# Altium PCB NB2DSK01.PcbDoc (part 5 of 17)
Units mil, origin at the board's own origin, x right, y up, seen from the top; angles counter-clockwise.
Board outline 11815 x 6500.03 mil, 8 copper layers (Top Layer, MidLayer1, MidLayer2, GND, PWR, MidLayer3, MidLayer4, Bottom Layer), stack 74.62 mil thick; 798 components, 1002 nets, 3927 pads, 3182 vias.
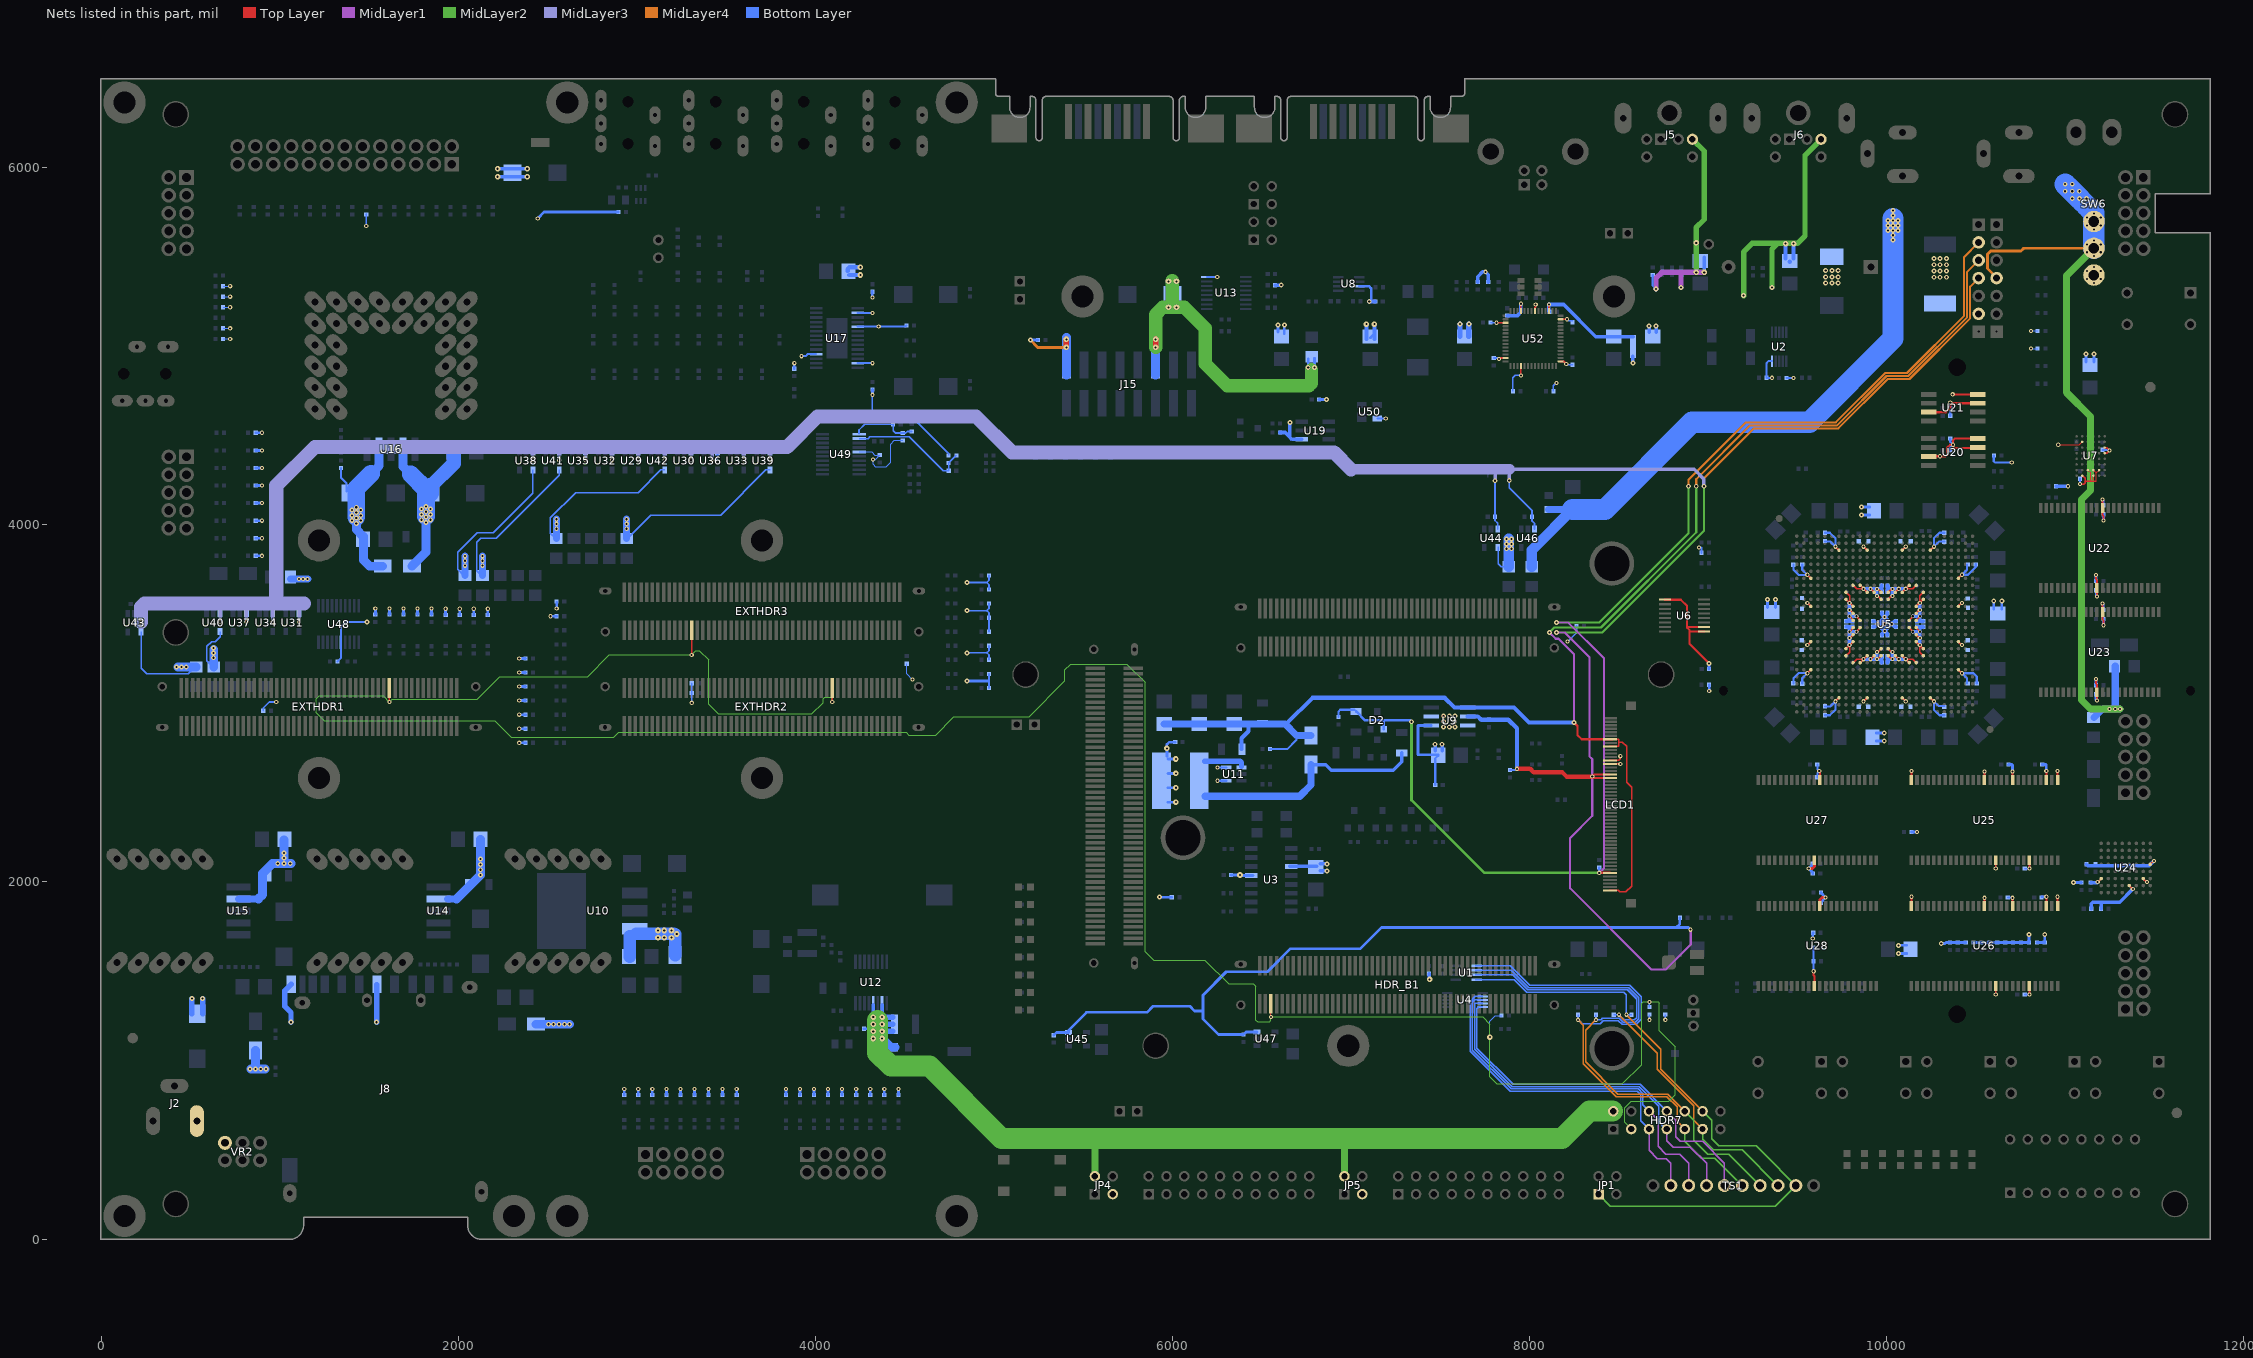
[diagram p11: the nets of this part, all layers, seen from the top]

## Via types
v1: diameter 23.62, hole 11.81, Top Layer to Bottom Layer, tented both sides, 1950 vias
v2: diameter 27.56, hole 11.81, Top Layer to Bottom Layer, tented both sides, 679 vias
v3: diameter 23.62, hole 11.81, Top Layer to Bottom Layer, 194 vias
v4: diameter 31.5, hole 11.81, Top Layer to Bottom Layer, tented both sides, 178 vias
v5: diameter 21.65, hole 11.81, Top Layer to Bottom Layer, tented both sides, 67 vias
v6: diameter 23.62, hole 11.81, Top Layer to Bottom Layer, tented bottom, 53 vias
v7: diameter 26, hole 11.81, Top Layer to Bottom Layer, tented both sides, 21 vias
v8: diameter 26, hole 11.81, Top Layer to Bottom Layer, 13 vias
v9: diameter 28, hole 11.81, Top Layer to Bottom Layer, 8 vias
v10: diameter 25.59, hole 11.81, Top Layer to Bottom Layer, tented both sides, 7 vias
v11: diameter 39.37, hole 11.81, Top Layer to Bottom Layer, tented both sides, 5 vias
v12: diameter 30, hole 11.81, Top Layer to Bottom Layer, 3 vias
v13: diameter 30, hole 11.81, Top Layer to Bottom Layer, tented both sides, 2 vias
v14: diameter 23, hole 11.81, Top Layer to Bottom Layer, tented both sides, 1 vias
v15: diameter 26.56, hole 11.81, Top Layer to Bottom Layer, tented both sides, 1 vias

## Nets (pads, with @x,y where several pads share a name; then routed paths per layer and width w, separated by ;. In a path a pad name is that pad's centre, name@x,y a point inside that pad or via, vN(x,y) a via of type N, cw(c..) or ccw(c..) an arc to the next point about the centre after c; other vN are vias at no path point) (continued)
3V3: C10.1 C11.1 C14.1 C15.1 C54.1 C55.1 C56.1 C57.1 C58.1 C59.1 C60.1 C61.1 C62.1 C63.1 C64.1 C65.1 C66.1 C67.1 C68.1 C69.1 C70.1 C71.1 C72.1 C73.1 C74.1 C75.1 C76.1 C77.1 C78.1 C79.1 C80.1 C81.1 C82.1 C83.1 C84.1 C85.1 C86.1 C87.1 C88.1 C89.1 C90.1 C91.1 C92.1 C93.1 C94.1 C95.1 C96.1 C97.1 C98.1 C99.1 C100.1 C101.1 C102.1 C103.1 C104.1 C105.1 C106.1 C107.1 C108.1 C109.1 C110.1 C111.1 C112.1 C113.1 C117.1 C121.1 C122.1 C123.1 C124.1 C125.1 C126.1 C154.1 C157.1 C158.1 C161.1 C162.1 C167.1 C168.1 C199.1 C200.2 C201.1 C202.2 C203.1 C204.1 C205.1 C206.1 C207.1 C208.1 C209.1 C210.1 C211.1 C212.1 C213.1 C214.1 C215.1 C216.1 C217.1 C218.1 C219.1 C220.1 C221.1 C222.1 C223.1 C224.1 C225.1 C226.1 C227.1 C228.1 C229.1 C230.1 C231.1 C232.1 C233.1 C234.1 C254.1 C255.1 C263.2 C264.2 C265.2 C266.1 C267.1 C268.1 D6.2 D7.2 D8.1 J8.4 J8.COM J15.16 JP4.3 JP5.3 LCD1.37 LCD1.38 NT5.1 R1.2 R6.1 R7.1 R10.2 R12.1 R18.2 R20.1 R34.2 R47.2 R52.1 R79.2 R135.2 R137.2 R142.2 R143.2 R144.2 R145.2 R146.2 R147.2 R148.2 R149.2 R150.2 R151.2 R152.2 R153.1 R154.1 R155.2 R156.1 R157.2 R158.1 R159.1 R160.2 R171.1 R172.1 R173.1 R177.1 R183.2 R190.2 R191.2 R192.2 R193.2 R198.2 R199.2 R200.2 R201.2 R206.2 R208.2 R209.2 R210.2 R211.2 R216.2 R217.2 R218.2 R219.2 R224.2 R226.2 R227.2 R228.2 R229.2 R234.2 R235.2 R236.2 R237.2 R242.2 R244.2 R245.2 R246.2 R247.2 R252.2 R253.2 R254.2 R255.2 R260.2 R262.2 R263.2 R264.2 R265.2 R270.2 R271.2 R272.2 R273.2 R278.2 R280.2 R281.2 R282.2 R283.2 R288.2 R289.2 R290.2 R291.2 R296.1 R297.2 R298.2 R299.2 R300.2 R303.1 R304.1 R314.2 R316.2 R318.1 R319.1 TP12.1 U2.10 U3.3 U3.13 U5.AD7 U5.AD11 U5.AD16 U5.AD20 U5.C7 U5.C11 U5.C16 U5.C20 U5.G3 U5.G24 U5.H9 U5.H10 U5.H17 U5.H18 U5.J8 U5.J11 U5.J12 U5.J13 U5.J14 U5.J15 U5.J16 U5.J19 U5.K8 U5.K13 U5.K14 U5.K19 U5.L3 U5.L9 U5.L18 U5.L24 U5.M9 U5.M18 U5.N9 U5.N10 U5.N17 U5.N18 U5.P9 U5.P10 U5.P17 U5.P18 U5.R9 U5.R18 U5.T3 U5.T9 U5.T18 U5.T24 U5.U8 U5.U13 U5.U14 U5.U19 U5.V8 U5.V11 U5.V12 U5.V13 U5.V14 U5.V15 U5.V16 U5.V19 U5.W9 U5.W10 U5.W17 U5.W18 U5.Y3 U5.Y24 U6.1 U6.9 U6.10 U7.B2 U7.C6 U7.D6 U7.G3 U7.G4 U7.G5 U7.H2 U7.H4 U8.3 U13.16 U14.2 U15.2 U16.4 U19.4 U20.3 U20.7 U20.8 U21.3 U21.7 U21.8 U22.11 U22.33 U23.11 U23.33 U24.D8 U24.F1 U24.F7 U24.G5 U25.1 U25.3 U25.9 U25.14 U25.27 U25.43 U25.49 U26.1 U26.3 U26.9 U26.14 U26.27 U26.43 U26.49 U27.11 U27.33 U28.11 U28.33 U38.4 U39.4 U40.4 U44.4 U48.15 U49.15 U50.4 U52.7 U52.11 U52.17 U52.27 U52.32 U52.43 U52.55 | length 26546.1
  Top Layer w5: v1(10960.63,4448.82) 11078.74,4448.82 U7.B2@11094.49,4464.57 ; U7.G3@11125.98,4307.09 11141.73,4291.34 11141.73,4244.1 ; 11157.48,4246.62 U7.H4@11157.48,4275.59 ; U7.G4@11157.48,4307.09 11173.23,4291.34 ; 11173.23,4244.1 11173.23,4291.34 ; U7.G5@11188.98,4307.09 11173.23,4291.34
  Top Layer w7.87: v1(7950.79,4836.61) U52.32@7950.79,4885.24 ; U52.55@8177.76,5151.57 v1(8208.68,5151.57) ; LCD1.37@8448.82,2661.42 v1(8507.87,2661.42) ; LCD1.38@8448.82,2681.1 8500,2681.1 8507.87,2688.98 v1(8507.87,2704.73) ; 8803.15,3581.06 8846.46,3581.06 ; v1(9555.12,3169.29) U5.Y3@9574.8,3188.98 ; v1(9555.12,3326.77) U5.T3@9574.8,3346.46 ; v1(9555.12,3562.99) U5.L3@9574.8,3543.31 ; v1(9555.12,3720.47) U5.G3@9574.8,3700.79 ; v1(9712.6,3011.81) U5.AD7@9732.28,3031.5 ; v1(9712.6,3877.95) U5.C7@9732.28,3858.27 ; U5.V8@9771.65,3267.72 9791.34,3287.4 v1(9791.34,3326.77) ; U5.U8@9771.65,3307.09 v1(9791.34,3326.77) ; U5.K8@9771.65,3582.68 v1(9791.34,3562.99) ; U5.J8@9771.65,3622.05 9791.34,3602.36 v1(9791.34,3562.99) ; v1(9791.34,3366.14) U5.R9@9811.02,3385.83 ; v5@9791.34,3402.76 U5.P9@9811.02,3425.2 ; v5@9791.34,3487.01 U5.N9@9811.02,3464.57 ; v1(9791.34,3523.62) U5.M9@9811.02,3503.94 ; U5.W9@9811.02,3228.35 9830.71,3248.03 v1(9870.08,3248.03) ; U5.T9@9811.02,3346.46 v1(9791.34,3326.77) ; U5.L9@9811.02,3543.31 v1(9791.34,3562.99) ; U5.H9@9811.02,3661.42 9830.71,3641.73 v1(9870.08,3641.73) ; v5@9830.71,3403.15 U5.P10@9850.39,3425.2 ; v5@9830.71,3486.62 U5.N10@9850.39,3464.57 ; U5.W10@9850.39,3228.35 v1(9870.08,3248.03) ; U5.H10@9850.39,3661.42 v1(9870.08,3641.73) ; v1(9870.08,3011.81) U5.AD11@9889.76,3031.5 ; v1(9870.08,3877.95) U5.C11@9889.76,3858.27 ; U5.V11@9889.76,3267.72 v1(9870.08,3248.03) ; U5.J11@9889.76,3622.05 v1(9870.08,3641.73) ; v1(9909.45,3248.03) U5.V12@9929.13,3267.72 ; v1(9909.45,3641.73) U5.J12@9929.13,3622.05 ; v5@9948.82,3248.03 U5.V13@9968.5,3267.72 ; v5@9948.82,3287.4 U5.U13@9968.5,3307.09 ; v5@9948.82,3602.36 U5.K13@9968.5,3582.68 ; v5@9948.82,3641.73 U5.J13@9968.5,3622.05 ; U5.V14@10007.87,3267.72 v5@10027.56,3248.03 ; U5.U14@10007.87,3307.09 v5@10027.56,3287.4 ; U5.K14@10007.87,3582.68 v5@10027.56,3602.36 ; U5.J14@10007.87,3622.05 v5@10027.56,3641.73 ; U5.V15@10047.24,3267.72 v1(10066.93,3248.03) ; U5.J15@10047.24,3622.05 v1(10066.93,3641.73) ; U5.AD16@10086.61,3031.5 v1(10106.3,3011.81) ; U5.V16@10086.61,3267.72 v1(10106.3,3248.03) ; U5.J16@10086.61,3622.05 v1(10106.3,3641.73) ; U5.C16@10086.61,3858.27 v1(10106.3,3877.95) ; U5.W17@10125.98,3228.35 v1(10106.3,3248.03) ; U5.P17@10125.98,3425.2 v5@10145.67,3405.51 ; U5.N17@10125.98,3464.57 v5@10145.67,3484.25 ; U5.H17@10125.98,3661.42 v1(10106.3,3641.73) ; U5.W18@10165.35,3228.35 10145.67,3248.03 v1(10106.3,3248.03) ; U5.T18@10165.35,3346.46 v1(10185.04,3326.77) ; U5.R18@10165.35,3385.83 v1(10185.04,3366.14) ; U5.P18@10165.35,3425.2 v5@10185.04,3405.51 ; U5.N18@10165.35,3464.57 v5@10185.04,3485.83 ; U5.M18@10165.35,3503.94 v1(10185.04,3523.62) ; U5.L18@10165.35,3543.31 v1(10185.04,3562.99) ; U5.H18@10165.35,3661.42 10145.67,3641.73 v1(10106.3,3641.73) ; U5.V19@10204.72,3267.72 10185.04,3287.4 v1(10185.04,3326.77) ; U5.U19@10204.72,3307.09 v1(10185.04,3326.77) ; U5.K19@10204.72,3582.68 v1(10185.04,3562.99) ; U5.J19@10204.72,3622.05 10185.04,3602.36 v1(10185.04,3562.99) ; U5.AD20@10244.09,3031.5 v1(10263.78,3011.81) ; U5.C20@10244.09,3858.27 v1(10263.78,3877.95) ; U5.Y24@10401.58,3188.98 v1(10421.26,3169.29) ; U5.T24@10401.58,3346.46 v1(10421.26,3326.77) ; U5.L24@10401.58,3543.31 v1(10421.26,3562.99) ; U5.G24@10401.58,3700.79 v1(10421.26,3720.47) ; v1(11082.68,4228.35) 11102.36,4228.35 11110.24,4236.22 11110.24,4240.24 11110.24,4259.84 U7.H2@11094.49,4275.59 ; v1(11181.1,1999.82) U24.F1@11200.79,2019.51 ; U7.D6@11220.47,4401.58 11232.28,4401.58 v1(11248.03,4417.32) 11232.28,4433.07 U7.C6@11220.47,4433.07 ; U24.G5@11358.27,1980.14 v1(11377.95,1960.45) ; U24.F7@11437.01,2019.51 v1(11456.69,1999.82) ; U24.D8@11476.38,2098.25 v1(11496.06,2117.93)
  Top Layer w8: 11110,4240 11110.24,4240.24 11114.1,4244.1 11141.73,4244.1 11173.23,4244.1
  Top Layer w9.84: U52.11@7950.79,5193.9 U52.11@7950.78,5197.78 v1(7950.79,5238.19) ; U52.43@8173.01,4915.5 U52.43@8174.01,4915.5 8190.8,4915.5 v1(8204.72,4901.58) ; U26.14@10547.25,1866.14 v1(10547.24,1911.42) ; U25.14@10547.25,2570.87 v1(10547.24,2618.11) ; v1(10610.24,1370.08) U26.43@10610.24,1417.32 ; v1(10610.24,2074.8) U25.43@10610.24,2122.05 ; U26.9@10704.73,1866.14 v1(10704.72,1911.42) ; U25.9@10704.73,2570.87 v1(10704.72,2618.11) ; v1(10799.21,1370.08) U26.49@10799.21,1417.32 ; v1(10799.21,2074.8) U25.49@10799.21,2122.05 ; v1(11177.17,3015.75) U23.11@11177.17,3062.99 11177.17,3106.69 11172.24,3111.61 v1(11172.24,3136.81) v1@11177.17,3131.89 ; v1(11177.17,3598.43) U22.11@11177.17,3645.67 11177.17,3691.39 11172.24,3696.31 v1(11172.24,3719.49) v1@11177.17,3714.57 ; v1@11208.66,3442.91 v1(11213.58,3437.99) 11213.58,3463.86 11208.66,3468.78 U23.33@11208.66,3511.81 v1(11208.66,3559.06) ; v1(11208.66,4141.73) U22.33@11208.66,4094.49 11208.66,4054.11 11213.58,4049.19 v1(11213.58,4024.61)
  Top Layer w10: v1(7813.68,5131.89) U52.17@7861.61,5131.89 ; v1(7828.68,4928.45) 7835.41,4935.19 U52.27@7865.35,4935.19 ; U52.7@8029.52,5197.78 8029.52,5217.52 8033.68,5221.68 v1(8033.68,5233.45)
  Top Layer w11.81: v1(9590.55,1500.14) 9590.55,1477.45 9594.49,1473.51 U28.33@9594.49,1417.32 ; v1(9622.05,2622.05) 9625.98,2618.11 U27.11@9625.98,2570.87 ; U26.27@10137.8,1866.14 v1(10137.8,1917.32) ; U25.27@10137.8,2570.87 v1(10137.8,2622.05) ; U20.3@10208.66,4384.65 10234.25,4384.65 v1(10297.64,4384.65) 10328.65,4384.65 10339,4395 10339,4433 10354.82,4448.82 v1(10371.06,4448.82) ; U26.3@10893.7,1866.14 v1(10893.7,1917.32) ; U25.3@10893.7,2570.87 v1(10893.7,2622.05) ; U26.1@10956.69,1866.14 v1(10956.69,1917.32) ; U25.1@10956.69,2570.87 v1(10956.69,2622.05)
  Top Layer w12: U6.1@8757.87,3581.06 8846.46,3581.06 8881.89,3545.63 8881.89,3423.11 ; 8895,3410 8895,3333.51 v2(9004.92,3223.58) ; U6.9@8976.38,3401.93 8903.07,3401.93 8881.89,3423.11 ; U6.10@8976.38,3427.52 8886.3,3427.52 8881.89,3423.11 ; U21.3@10234.25,4631.1 10332.1,4631.1 10356,4655 v1@10356,4684.36 ; v1(10355.32,4685.04) v1@10356,4684.36 ; v1(10369.1,4731.1) U21.8@10509.84,4731.1 ; U20.8@10509.84,4483.07 10381.07,4483.07 10371.06,4473.06 v1(10371.06,4448.82) 10371.06,4439.94 10381,4430 10509.84,4430 U20.7@10510,4430 ; U21.7@10509.84,4681.1 10359.25,4681.1 v1@10356,4684.36
  Top Layer w15.75: v1(9562.99,2074.8) 9582.68,2074.8 9594.49,2086.62 U27.33@9594.49,2122.05 ; U28.11@9625.98,1866.14 9625.98,1901.57 9637.8,1913.39 v1(9657.48,1913.39)
  Top Layer w30: v4(5405.51,4994.27) v4(5405.51,5039.19)
  MidLayer1 w30: v4(5405.51,4994.27) v4(5405.51,5039.19)
  MidLayer2 w30: v4(5405.51,4994.27) v4(5405.51,5039.19)
  MidLayer4 w15.75: v2(5204.2,5035.42) 5245.35,4994.27 v4(5405.51,4994.27)
  MidLayer4 w30: v4(5405.51,4994.27) v4(5405.51,5039.19)
  MidLayer3 w30: v4(5405.51,4994.27) v4(5405.51,5039.19)
  Bottom Layer w5: R300.2@682.6,5041.73 v1(722.36,5041.73) ; R299.2@682.6,5100.79 v1(722.36,5100.79) ; R298.2@682.6,5218.9 v1(722.36,5218.9) ; R297.2@682.6,5277.95 v1(722.36,5277.95) ; R296.1@682.6,5337.01 v1(722.36,5337.01) ; v1(10808,4987.57) R304.1@10845.4,4987.57 ; v1(10808,5086) R303.1@10845.4,5086
  Bottom Layer w7: U49.15@4244.37,4408.46 4315.94,4408.46 4333.66,4390.75 C254.1@4360.24,4390.75 4335.63,4366.14 v1(4322.83,4366.14) 4322.83,4338.58 4334.65,4326.77 4397.64,4326.77 4421.26,4350.39 4421.26,4452.76 4441.12,4472.62 R183.2@4489.11,4472.62 ; R144.2@4511.81,3222.3 4511.81,3165.35 v1(4543.31,3133.86)
  Bottom Layer w7.87: R173.1@625.98,3204.72 591.61,3239.09 591.61,3319.96 618.11,3346.46 637.8,3346.46 665.55,3374.21 U40.4@665.55,3401.94 ; U48.15@1342.4,3342.34 U48.15@1342.5,3342.24 ; R34.2@1482.28,5742.13 1484.25,5740.16 R34.2@1484.25,5738.66 v1@1484.25,5677.17 ; R171.1@2035.43,3712.6 2034.45,3713.58 1996.06,3751.97 1996.06,3846.46 2106.3,3956.69 2196.85,3956.69 2417.52,4177.36 U38.4@2417.52,4307.45 ; R172.1@2944.88,3921.26 3078.74,4055.12 3468.5,4055.12 3720.83,4307.45 U39.4@3746.26,4307.45 ; U44.4@7822.83,3877.95 7822.83,3874.38 7822.83,3783.46 7840.55,3765.75 R177.1@7883.86,3765.75 ; R316.2@7905.98,4748.03 7905.98,4823.31 7919.29,4836.61 v1(7950.79,4836.61) ; R314.2@8133.39,4748.03 8133.39,4779.05 v1(8149.61,4795.28) ; v1(8670.97,1228.01) R6.1@8670.97,1256.86 ; v1(8759.97,1228.01) R7.1@8759.97,1256.86 ; v5@10145.67,3404.33 v5@10145.67,3405.51 ; C95.1@10166.34,3429.13 C95.1@10169.29,3429.13 10203.69,3429.13 C58.1@10204.01,3429.45
  Bottom Layer w9.84: R142.2@907.5,2958.45 907.5,2974.43 940.94,3007.87 v1(980.32,3007.87) ; v1(3307.5,3003.45) R20.1@3307.5,3058.45 R143.2@3307.5,3113.45 ; v2(4849.58,3283.44) 4959.61,3283.44 ; v2(4849.58,3519.66) 4959.61,3519.66 ; v2(4849.58,3677.14) 4959.61,3677.14 ; R209.2@4971.97,3086.61 R208.2@4971.97,3165.35 ; R211.2@4971.97,3244.1 4971.97,3271.13 4959.64,3283.47 4971.97,3295.8 R210.2@4971.97,3322.84 ; R216.2@4971.97,3401.58 R217.2@4971.97,3480.32 4971.97,3507.35 4959.64,3519.69 4971.97,3532.02 R219.2@4971.97,3559.06 ; R218.2@4971.97,3637.8 4971.97,3664.83 4959.64,3677.17 4971.97,3689.5 R224.2@4971.97,3716.54 ; v1(8204.72,4901.58) 8209.65,4896.65 C264.2@8240.16,4896.65 ; v1(8208.68,5151.57) 8217.54,5142.72 C265.2@8240.16,5142.72 ; v1(8212.6,3346.46) 8262.5,3396.36 R18.2@8262.5,3433.45 ; v1@10355.32,4684.06 v1(10355.32,4685.04) ; C222.1@10772.64,1370.08 v1(10799.21,1370.08) ; C220.1@10772.64,2074.8 v1(10799.21,2074.8) ; v1(11208.66,4141.73) 11213.58,4136.81 C207.1@11213.58,4110.24
  Bottom Layer w10: C267.1@7782.48,5131.89 v1(7813.68,5131.89) ; C268.1@7799.21,4934.06 7823.08,4934.06 v1(7828.68,4928.45)
  Bottom Layer w11.81: U50.4@7146.86,4596.13 v1(7194.1,4596.13) ; v1(8949,3872.8) 8960,3872.8 8962.1,3870.7 R159.1@8962.1,3843.38 ; v1(9356.91,4823.54) C11.1@9326.4,4823.54 ; U2.10@9358.29,4916.76 9336.99,4916.76 9326.4,4906.17 ; R1.2@9438.61,4823 R1.2@9439.13,4823 v1(9477,4823) ; C233.1@9589.57,1631.93 C229.1@9589.57,1556.18 ; v1(9590.55,1500.14) 9589.57,1501.13 C229.1@9589.57,1556.18 ; C229.1@9590.55,1555.19 C229.1@9589.57,1556.18 ; C232.1@9611.22,2586.61 9611.22,2609.25 9622.05,2620.08 v1(9622.05,2622.05) 9611.22,2632.87 C228.1@9611.22,2657.48 ; C199.1@10355.32,4417.32 10355.32,4435.04 10369.09,4448.82 v1(10371.06,4448.82) 10355.32,4464.57 C202.2@10355.32,4484.25 ; C200.2@10355.29,4611.45 C201.1@10355.32,4654.74 v1(10355.32,4685.04) ; C221.1@10678.15,1913.39 v1@10702.76,1913.39 ; C225.1@10866.14,1917.32 10867.13,1917.32 v1(10893.7,1917.32) ; v1(11082.68,4228.35) C121.1@11082.68,4258.86 ; C204.1@11172.24,3633.86 11172.24,3603.35 v1(11177.17,3598.43) ; v1(11208.66,3559.06) 11213.58,3554.13 C208.1@11213.58,3523.62 ; C122.1@11208.66,4420.28 11245.08,4420.28 v1(11248.03,4417.32) ; C11.1@9326.4,4823.54 9326.4,4906.17 ; C11.1@9326.4,4823.54 9326.4,4906.17
  Bottom Layer w12: C255.1@1322.76,3234.1 1342.5,3253.83 U48.15@1342.5,3342.24 1342.5,3429.5 1370,3457 v2(1489,3457) ; R79.2@1343.68,4318.67 1343.68,4262.92 1374.7,4231.9 C168.1@1374.7,4188.5 ; U13.16@6192.59,5388.78 v1(6250.66,5388.78) ; C75.1@9476.76,3113.03 9476.77,3139.94 9508.08,3171.26 v1@9555.12,3171.26 ; C106.1@9476.76,3776.74 9476.76,3749.83 9508.08,3718.51 v1@9555.12,3718.51 ; C98.1@9526.97,3110.91 9526.97,3141.14 v1(9555.12,3169.29) ; C80.1@9526.97,3778.86 9526.97,3748.62 v1(9555.12,3720.47) ; C81.1@9654.21,2983.66 9684.45,2983.66 v1(9712.6,3011.81) 9712.6,2964.77 9681.28,2933.45 C99.1@9654.37,2933.45 ; C78.1@9654.21,3906.1 9654.35,3906.1 9684.45,3906.1 v1(9712.6,3877.95) 9712.6,3925 9681.28,3956.31 C89.1@9654.37,3956.31 ; C88.1@10322.01,2933.45 10295.1,2933.45 10263.78,2964.77 v1(10263.78,3011.81) 10290.75,2984.84 10322.01,2984.84 C70.1@10322.17,2984.84 ; C87.1@10322.01,3956.31 10295.1,3956.31 10263.78,3925 v1(10263.78,3877.95) 10291.93,3906.1 C79.1@10322.17,3906.1 ; C69.1@10449.41,3110.91 10449.41,3111.12 10449.41,3141.14 v1(10421.26,3169.29) 10485.57,3169.29 10503.94,3150.92 C108.1@10503.94,3111.22 ; C73.1@10449.41,3778.86 10449.41,3778.78 10449.41,3748.62 v1(10421.26,3720.47) 10454.72,3720.47 10498.68,3764.43 C101.1@10498.68,3778.78 C101.1@10498.68,3779.25 ; R52.1@10599.28,4388.25 10599.28,4356.72 10606,4350 v1(10700,4350)
  Bottom Layer w14: U8.3@7045.11,5336.69 7099.93,5336.69 7112.33,5324.29 7112.33,5261.76 v2(7101.62,5251.06)
  Bottom Layer w15: v2(4849.58,3125.96) 4969.46,3125.96
  Bottom Layer w15.75: R290.2@865.67,3826.77 v1(900.12,3826.77) ; R291.2@865.67,3925.2 v1(900.12,3925.2) ; R289.2@865.67,4023.62 v1(900.12,4023.62) ; R288.2@865.67,4122.05 v1(900.12,4122.05) ; R283.2@865.67,4220.47 v1(900.12,4220.47) ; R282.2@865.67,4318.9 v1(900.12,4318.9) ; R280.2@865.67,4417.32 v1(900.12,4417.32) ; R281.2@865.67,4515.75 v1(900.12,4515.75) ; R206.2@1535.43,3497.56 v1(1535.43,3532.01) ; R200.2@1614.17,3497.56 v1(1614.17,3532.01) ; R201.2@1692.91,3497.56 v1(1692.91,3532.01) ; R199.2@1771.65,3497.56 v1(1771.65,3532.01) ; R198.2@1850.39,3497.56 v1(1850.39,3532.01) ; R192.2@1929.13,3495.59 v1(1929.13,3530.04) ; R193.2@2007.87,3495.59 v1(2007.87,3530.04) ; R190.2@2086.61,3495.59 v1(2086.61,3530.04) ; R191.2@2165.35,3495.59 v1(2165.35,3530.04) ; v1(2341.61,2779.53) R242.2@2376.06,2779.53 ; v1(2341.61,2858.27) R236.2@2376.06,2858.27 ; v1(2341.61,2937.01) R237.2@2376.06,2937.01 ; v1(2341.61,3015.75) R235.2@2376.06,3015.75 ; v1(2341.61,3094.49) R234.2@2376.06,3094.49 ; v1(2341.61,3173.23) R228.2@2376.06,3173.23 ; v1(2341.61,3251.97) R229.2@2376.06,3251.97 ; v1(2444.88,5716.54) 2480.32,5751.97 R135.2@2896.14,5751.97 ; v1(2516.42,3488.19) R227.2@2550.87,3488.19 ; v1(2550.87,3532.48) R226.2@2550.87,3566.93 ; R245.2@2929.13,806.61 v1(2929.13,841.06) ; R244.2@3007.87,806.61 v1(3007.87,841.06) ; R247.2@3086.61,806.61 v1(3086.61,841.06) ; R246.2@3165.35,806.61 v1(3165.35,841.06) ; R252.2@3244.09,806.61 v1(3244.09,841.06) ; R253.2@3322.83,806.61 v1(3322.83,841.06) ; R255.2@3401.57,806.61 v1(3401.57,841.06) ; R254.2@3480.32,806.61 v1(3480.32,841.06) ; R260.2@3559.06,806.61 v1(3559.06,841.06) ; R263.2@3834.65,806.61 v1(3834.65,841.06) ; R262.2@3913.39,806.61 v1(3913.39,841.06) ; R265.2@3992.13,806.61 v1(3992.13,841.06) ; R264.2@4070.87,806.61 v1(4070.87,841.06) ; R270.2@4149.61,806.61 v1(4149.61,841.06) ; R271.2@4228.35,806.61 v1(4228.35,841.06) ; R273.2@4307.09,806.61 v1(4307.09,841.06) ; R272.2@4385.83,806.61 v1(4385.83,841.06) ; R278.2@4464.57,806.61 v1(4464.57,841.06) ; v2@5200.26,5035.42 v2(5204.2,5035.42) R137.2@5246.52,5035.42 ; v2(5927.84,1915) R158.1@5995.64,1915 ; C14.1@6327.76,2039.37 v4@6374.02,2039.37 ; v4(6377.95,2039.37) v4@6374.02,2039.37 ; U3.13@6450.79,2037.01 U3.13@6440.95,2037.01 6377.95,2037.01 6376.38,2037.01 6375.98,2037.4 v4@6374.02,2039.37 ; C123.1@6590.61,5079.36 v2(6590.61,5118.73) ; C123.1@6626.05,5071.48 v2(6626.05,5118.73) ; C125.1@6820.68,4702 v2(6863,4702) ; C124.1@7107.83,5047.86 7111.76,5051.8 C124.1@7127.51,5067.55 ; C117.1@9004.92,3192.91 v2(9004.92,3223.58) ; v1(9005.4,3070.4) R47.2@9005.4,3104.85 ; C57.1@9332.73,3536.55 v2(9332.73,3581.55) ; C57.1@9377.73,3536.55 v2(9377.73,3581.55) ; v1(9585.33,1683.84) 9585.33,1712.38 C226.1@9588.28,1715.33 ; C231.1@9585.63,2047.24 9585.63,2052.17 v1(9562.99,2074.8) 9585.63,2097.44 C227.1@9585.63,2102.36 ; C234.1@9630.91,1881.89 9630.91,1886.81 v1(9657.48,1913.39) 9630.91,1939.96 C230.1@9630.91,1940.95 ; v2(9859.48,4055.87) C56.1@9904.48,4055.87 ; v2(9859.48,4100.87) C56.1@9904.48,4100.87 ; C54.1@9941,2788.98 v2(9986,2788.98) ; C54.1@9941,2833.98 v2(9986,2833.98) ; v2(10066.54,1600.28) C218.1@10111.54,1600.28 ; v2(10066.54,1645.28) C218.1@10111.54,1645.28 ; C224.1@10138.89,2280.7 v1(10169.4,2280.7) ; v2(10305,1655) 10327,1655 10332.48,1660.48 R153.1@10353.41,1660.48 R155.2@10441.99,1660.48 ; R145.2@10486.28,1660.48 R146.2@10530.57,1660.48 R147.2@10574.86,1660.48 R148.2@10619.15,1660.48 R149.2@10663.44,1660.48 R150.2@10707.73,1660.48 R151.2@10752.03,1660.48 R152.2@10796.32,1660.48 v2(10796.32,1706.14) ; C55.1@10599.19,3528.68 v2(10599.19,3573.68) ; C55.1@10644.19,3528.68 v2(10644.19,3573.68) ; C219.1@10682.09,2656.5 C219.1@10682.09,2657.48 10701.48,2657.48 10704.72,2654.24 v1(10704.72,2618.11) ; R156.1@10840.61,1660.48 R157.2@10884.9,1660.48 v2(10884.9,1706.14) ; C223.1@10871.06,2657.48 10890.46,2657.48 10893.7,2654.24 v1(10893.7,2622.05) ; v2(11044.88,1996.87) C212.1@11090.55,1996.87 ; C217.1@11116,4913 v2(11116,4958) ; C217.1@11161,4913 v2(11161,4958) ; C210.1@11172.24,3102.36 v1(11172.24,3136.81) ; C209.1@11172.24,3685.04 v1(11172.24,3719.49) ; C206.1@11173.23,3050.2 C206.1@11172.24,3051.18 11172.24,3020.67 v1(11177.17,3015.75) ; v1(11213.58,3437.99) C205.1@11213.58,3472.44 ; v1(11213.58,4024.61) C203.1@11213.58,4059.06
  Bottom Layer w19.68: U3.3@6655.51,2087.01 U3.3@6665.35,2087.01 6801.5,2087.01 C15.1@6808.66,2087.01 ; C15.1@6828.7,2061.9 v2(6864.13,2061.9) ; C15.1@6828.7,2101.27 v2(6864.13,2101.27) ; v2(8578,4907.57) NT5.1@8578,4943 ; C10.1@8668.93,5079 v2(8668.93,5114.43) ; C10.1@8708.3,5079 v2(8708.3,5114.43) ; R12.1@10948.35,4216.54 v1(11015.75,4216.54) ; C215.1@11141.73,1996.87 11178.15,1996.87 v1(11181.1,1999.82) ; C216.1@11144.78,1850.28 11144.78,1877.28 11154,1886.5 11206.6,1886.5 ; C213.1@11199.85,1850.28 11199.85,1879.75 11206.6,1886.5 ; v1(11377.95,1960.45) 11304,1886.5 11206.6,1886.5
  Bottom Layer w20: C154.1@6574.48,5342.52 v2(6608.93,5342.52) ; R160.2@6601.98,4517.47 6630.53,4517.47 6657,4491 ; v2(6657,4573) 6657,4491 ; U19.4@6724.27,4478.53 6669.47,4478.53 6657,4491 ; v2(7101.62,5251.06) C126.1@7136.07,5251.06 ; R10.2@7436.99,1486.69 7436.99,1459.99 v13(7440,1455) ; R319.1@7708.78,5359.75 7708.78,5389.78 7736.32,5417.32 v1(7751.97,5417.32) 7767.9,5401.39 R318.1@7767.9,5359.75 ; C263.2@7874,5172.23 7932.23,5172.23 7950.79,5190.79 v1(7950.79,5238.19) ; C59.1@9772.64,3460.63 9773.35,3460.63 C105.1@9808.07,3460.63 ; C61.1@9773.03,3429.13 9773.35,3429.13 C85.1@9808.07,3429.14 ; v1(9791.34,3326.77) v1(9791.34,3366.14) v5(9791.34,3401.58) ; 9791.34,3428.8 v5(9791.34,3401.58) ; 9791.34,3461.11 v5(9791.34,3488.19) ; v1(9791.34,3562.99) v1(9791.34,3523.62) v5(9791.34,3488.19) ; v5(9830.71,3401.58) v5(9791.34,3401.58) ; v5(9830.71,3488.19) v5(9791.34,3488.19) ; v1(9870.08,3248.03) v1(9909.45,3248.03) v5(9944.88,3248.03) ; v1(9870.08,3641.73) v1(9909.45,3641.73) v5(9944.88,3641.73) ; C107.1@9924.54,3429.45 9933.68,3429.45 v5(9948.68,3444.45) ; C64.1@9924.54,3460.45 9932.68,3460.45 v5(9948.68,3444.45) ; v5(9944.88,3287.4) v5(9944.88,3248.03) ; v5(9944.88,3602.36) v5(9944.88,3641.73) ; 9971.86,3248.03 v5(9944.88,3248.03) ; 9972.16,3641.73 v5(9944.88,3641.73) ; C68.1@9972.44,3229.33 C100.1@9972.44,3264.76 C100.1@9972.44,3266.73 ; C86.1@9972.44,3623.03 C86.1@9972.44,3625 C60.1@9972.44,3660.43 ; C62.1@9972.68,3389.45 C62.1@9973.68,3390.45 ; C92.1@9972.68,3507.59 9972.68,3498.45 v5(9987.68,3483.45) ; C62.1@9973.68,3381.31 C62.1@9973.68,3390.45 ; v5@9988.19,3405.94 v5(9988.19,3444.88) v5@9988.19,3445.45 ; C110.1@10003.68,3381.31 10003.68,3390.45 v5(9988.68,3405.45) ; C93.1@10003.68,3507.59 10003.68,3499.45 v5(9987.68,3483.45) ; C67.1@10003.94,3229.33 C104.1@10003.94,3264.76 C104.1@10003.94,3266.73 ; C94.1@10003.94,3623.03 C94.1@10003.94,3625 C66.1@10003.94,3660.43 ; 10004.22,3641.73 v5(10031.5,3641.73) ; 10004.36,3248.03 v5(10031.5,3248.03) ; v5(10031.5,3287.4) v5(10031.5,3248.03) ; v5(10031.5,3602.36) v5(10031.5,3641.73) ; C63.1@10051.82,3429.45 10043.68,3429.45 v5(10027.68,3445.45) ; C96.1@10051.82,3460.45 10042.68,3460.45 v5(10027.68,3445.45) ; v1(10106.3,3248.03) v1(10066.93,3248.03) v5(10031.5,3248.03) ; v1(10106.3,3641.73) v1(10066.93,3641.73) v5(10031.5,3641.73) ; v5(10145.67,3401.58) v5(10185.04,3401.58) ; v5(10145.67,3488.19) v5(10185.04,3488.19) ; C91.1@10166.34,3460.63 10166.52,3460.45 10169.29,3460.45 C65.1@10204.01,3460.45 ; v1(10185.04,3326.77) v1(10185.04,3366.14) v5(10185.04,3401.58) ; 10185.04,3428.81 v5(10185.04,3401.58) ; 10185.04,3461.09 v5(10185.04,3488.19) ; v1(10185.04,3562.99) v1(10185.04,3523.62) v5(10185.04,3488.19) ; C211.1@11118.11,2099.23 11126.84,2090.5 11169.29,2090.5 11468.63,2090.5 v1(11496.06,2117.93) ; v5(9948.68,3444.45) 9987.68,3405.45 v5(9988.68,3405.45) ; v5(9948.68,3444.45) v5@9949.68,3445.45 ; v5@9949.68,3445.45 v5@9988.19,3445.45 ; v5@9949.68,3445.45 v5(9987.68,3483.45) ; C62.1@9973.68,3390.45 v5(9988.68,3405.45) ; v5(9987.68,3483.45) 9988.19,3482.94 v5@9988.19,3445.45 ; v5(9987.68,3483.45) 9989.68,3483.45 v5(10027.68,3445.45) ; v5@9988.19,3445.45 v5(10027.68,3445.45) ; v5(9988.68,3405.45) 10027.68,3444.45 v5(10027.68,3445.45)
  Bottom Layer w22: C124.1@7085.37,5041.55 7085.37,5055.73 v4(7085.37,5124.62) ; C124.1@7130.28,5041.55 7130.28,5055.73 v4(7130.28,5124.62)
  Bottom Layer w22.05: C95.1@10169.29,3429.13 C58.1@10203.69,3429.13
  Bottom Layer w30: v2(1063.19,1214.76) 1063.19,1268.95 1028.68,1303.45 1028.68,1391.6 J8.COM@1064.74,1427.67 ; v2(1542.52,1214.76) J8.4@1542.52,1426.11 ; C266.1@7609.76,5054.63 7609.76,5055.73 v2(7609.76,5124.63) ; C266.1@7659.76,5054.63 7659.76,5055.73 v2(7659.76,5124.63)
  Bottom Layer w39.37: U15.2@768.68,1905.38 880.61,1905.38 ; U14.2@1939,1905.38 1990.61,1905.38 ; R171.1@2037.4,3716.54 v1(2037.4,3771.65) v1(2037.4,3799.21) v1(2037.4,3824.8) ; R172.1@2942.91,3923.23 v1(2942.91,3978.35) v1(2942.91,4005.91) v1(2942.91,4031.5)
  Bottom Layer w49.21: R173.1@629.92,3204.72 v2(629.92,3255.91) v2(629.92,3283.46) v2@629.92,3303.15
  Bottom Layer w50: v2@838.68,953.45 v2(863.68,953.45) ; D7.2@863.68,1056.76 v2(863.68,953.45) ; 880.61,1905.38 903.68,1928.45 903.68,2034.68 903.68,2048.45 912.47,2057.25 958.68,2103.45 v2(988.68,2103.45) v2(1023.68,2103.45) ; v2@918.68,953.45 v2(893.68,953.45) v2(863.68,953.45) ; C162.1@1023.68,2235.46 v2(1023.68,2163.45) v2(1023.68,2133.45) v2(1023.68,2103.45) ; v2@1063.68,2103.45 v2(1058.68,2103.45) v2(1023.68,2103.45) ; v2(1428.68,4038.45) 1428.68,4023.45 v2(1428.68,4008.45) 1428.68,3974.4 C167.1@1468.68,3934.4 ; C167.1@1469.63,3918.45 1469.63,3802.51 1503.68,3768.45 D8.1@1576.99,3768.45 ; 1511.18,4285.95 1556.75,4331.52 U16.4@1556.75,4423.45 ; 1990.61,1905.38 v2(2123.68,2038.45) v2(2123.68,2068.45) v2(2123.68,2098.45) v2@2123.68,2123.45 ; C158.1@2122.74,2198.45 C158.1@2124.01,2238.45 v2(2123.68,2128.45) ; D6.2@2435.37,1203.45 v2(2505.68,1203.45) v2(2533.68,1203.45) v2(2563.68,1203.45) v2(2593.68,1203.45) v2(2623.68,1203.45) ; J15.16@5405.51,4838.98 v4@5405.51,5049.69
  Bottom Layer w59.06: R177.1@7883.86,3765.75 7883.86,3866.14 7883.86,3893.7 7883.86,3921.26 7883.86,3923.23
  Bottom Layer w100: v2@1428.68,4043.45 1428.68,4053.45 v2(1428.68,4068.45) 1428.68,4083.45 v2(1428.68,4098.45) 1428.68,4178.18 1428.68,4203.45 1511.18,4285.95
  other v1: 1484.25,5673.23
  other v2: 833.68,953.45 923.68,953.45 629.92,3311.02 7870.08,3866.14 7897.64,3866.14 7870.08,3893.7 7897.64,3893.7 7870.08,3921.26 7897.64,3921.26 1403.68,4023.45 1453.68,4023.45 1403.68,4053.45 1453.68,4053.45 1403.68,4083.45 1453.68,4083.45
3V3D: C260.2 R183.1 R188.2 U49.11 | length 371.9
  Bottom Layer w10: U49.11@4244.09,4511.81 4244.09,4531.5 4275.59,4562.99 R188.2@4435.51,4562.99 4435.51,4526.79 4447.32,4514.98 R183.1@4489.11,4514.98 4506.18,4514.98 4514.14,4522.94 C260.2@4538.92,4522.94
5V0: C1.1 C2.1 C3.1 C4.1 C135.1 C140.1 C141.1 C142.2 C146.2 C147.2 C165.1 C166.1 C169.1 C170.1 C193.1 C194.2 C195.2 C196.2 D4.2 D8.2 F2.1 F3.2 F4.2 F5.2 HDR7.2 J2.1 J5.4 J6.4 J15.6 JP4.2 JP5.2 L1.1 R66.2 R84.1 R85.1 R88.1 R89.1 R111.2 R174.1 R175.1 R176.1 R179.1 R182.2 SW6.1 SW6.2 TP1.1 U10.3 U11.4 U11.5 U12.2 U12.4 U16.2 U17.4 U17.16 U17.19 U17.27 U41.4 U42.4 U43.4 U46.4 VR2.3 | length 25873.9
  Top Layer w30: v4(5905.51,4994.27) v4(5905.51,5039.19)
  MidLayer1 w30: v4(5905.51,4994.27) v4(5905.51,5039.19) ; v2(8708,5321.7) 8708,5382.3 8740.22,5414.51 8847.7,5414.51 ; v2@8847.7,5330.77 8847.7,5414.51 ; v4(8977.7,5414.51) v4(8932.79,5414.52) 8847.7,5414.51
  MidLayer2 w30: v4(5905.51,4994.27) v4(5905.51,5039.19) ; J5.4@8911.42,6159.45 8978,6092.87 8978,5710.7 8932.79,5665.49 v4(8932.79,5579.33) v4(8932.79,5414.52) v4(8977.7,5414.51) ; v2(9198.54,5283.56) 9198.54,5528.44 9246.4,5576.3 9389,5576.3 ; v2(9357.32,5329.96) 9357.32,5544.62 9389,5576.3 ; J6.4@9631.89,6159.45 9542,6069.56 9542,5617.9 9500.4,5576.3 9478.64,5576.3 9433.72,5576.3 9389,5576.3
  MidLayer2 w39.37: JP4.2@5565.12,351.81 5565.12,545.12 ; JP5.2@6962.76,351.81 6962.76,557.24 ; SW6.2@11160.24,5549.13 11007.87,5396.77 11007.87,4740.16 11141.73,4606.3 11141.73,4192.91 11090.55,4141.73 11090.55,3019.68 11141.73,2968.5 v1(11248.03,2968.5) v1(11279.53,2968.5) v1(11307.09,2968.5)
  MidLayer2 w74.8: v4(5905.51,4994.27) 5905.51,5124.51 5905.51,5178.31 5945.2,5218 6065.1,5218 ; 5999,5369 5999,5363.65 5999,5218 6065.1,5218 ; 6778,4869 6778,4793 6764,4779 6307,4779 6182.8,4903.2 6182.8,5100.3 6065.1,5218
  MidLayer2 w118.11: 4348.68,1223.45 4348.68,1203.45 4348.68,1163.45 4348.68,1123.45 4348.68,1043.45 4423.63,968.5 4637.8,968.5 5043.31,562.99 8180.99,562.99 8334.54,716.54 HDR7.2@8464.64,716.54
  MidLayer4 w15.75: TP1.1@10614.94,5385.97 10565,5435.91 10565,5516 10582,5533 10751,5533 10767.13,5549.13 SW6.2@11160.24,5549.13
  MidLayer4 w30: v4(5905.51,4994.27) v4(5905.51,5039.19)
  MidLayer3 w30: v4(5905.51,4994.27) v4(5905.51,5039.19)
  Bottom Layer w7.87: U43.4@223.61,3400.9 223.61,3197.1 255.35,3165.35 488.19,3165.35 527.56,3204.72 529.53,3206.69 R176.1@531.5,3208.66 ; R174.1@2133.86,3712.6 2132.87,3713.58 2102.36,3744.09 2102.36,3901.57 2125.98,3925.2 2212.6,3925.2 2565.16,4277.76 U41.4@2565.16,4307.45 ; R175.1@2547.24,3921.26 2515.75,3952.76 2515.75,4039.37 2657.48,4181.1 3007.87,4181.1 3134.22,4307.45 U42.4@3155.71,4307.45 ; v1(4318.9,4728.35) 4318.9,4618.1 4349.7,4587.3 4557.8,4587.3 4745.8,4399.3 R182.2@4745.8,4389.29 ; R179.1@8011.81,3765.75 8011.81,3822.83 8027.76,3838.78 8027.76,3874.21 U46.4@8027.76,3874.38
  Bottom Layer w11.81: v1(3921.26,4944.88) 3944.88,4944.88 3956.69,4956.69 U17.4@4003.94,4956.69 ; U17.27@4236.22,4905.51 v1(4318.9,4905.51) ; U17.19@4236.22,5110.24 v1(4354.33,5110.24) 4503.17,5110.24 R111.2@4510.31,5117.37 ; U17.16@4236.22,5187.01 v1(4318.9,5187.01) ; v1(6251.97,2566.93) U11.4@6301.18,2566.93 ; v1(6251.97,2641.73) U11.5@6301.18,2641.73
  Bottom Layer w12: R84.1@8689.73,5399.33 8689.73,5339.97 v2(8708,5321.7) ; v2(8848.51,5329.96) R85.1@8848.51,5399.33 ; v2(9198.54,5283.56) R88.1@9198.54,5395.39 ; v2(9357.32,5329.96) R89.1@9357.32,5395.39
  Bottom Layer w14.17: v1(4318.9,5273.62) C196.2@4318.9,5306.1 C196.2@4318.9,5307.09 ; v4(5968.5,2748.03) 5968.5,2770.41 5981.56,2783.47 C141.1@6014.76,2783.47 6014.18,2782.88 C141.1@6003.35,2782.88
  Bottom Layer w15: R66.2@4271.86,1178.45 v4@4323.68,1178.45
  Bottom Layer w15.75: C194.2@3881.89,4875 v1(3881.89,4905.51) ; v1(4318.9,4728.35) C195.2@4318.9,4758.86 ; L1.1@5968.5,2704.73 v4(5968.5,2748.03) ; L1.1@5975.4,2446.93 v4(6018.71,2446.93) ; L1.1@5975.4,2527.66 v4(6018.71,2527.66) ; L1.1@5975.4,2608.4 v4(6018.71,2608.4) ; L1.1@5975.4,2689.14 v4(6018.71,2689.14) ; v2(6759.83,4881.88) F2.1@6759.83,4929.12 ; v2(6795.26,4881.88) F2.1@6795.26,4933.06
  Bottom Layer w20: v4@4324.18,1228.95 4324.18,1243.45 U12.4@4324.18,1313.45 ; v4@4373.68,1238.45 v4@4373.88,1238.65 ; v4(4373.68,1243.45) U12.2@4373.68,1313.45
  Bottom Layer w22: v4(2220.02,5949.69) 2303.07,5949.69 v4(2386.16,5949.69) ; v4(2220.02,5994.61) 2303.07,5994.61 v4(2386.16,5994.61) ; v4(5977.08,5218) 5977.08,5290.81 v4(5977.08,5363.65) ; v4(6022,5218) 6022,5290.81 v4(6022,5363.65) ; v4(8932.79,5414.52) 8932.79,5477.21 C169.1@8932.79,5497.59 ; C169.1@8932.79,5496.26 v4(8932.79,5579.33) ; v4(8977.7,5414.51) 8977.7,5477.21 C169.1@8977.7,5497.59 ; C170.1@9433.72,5492.33 v4(9433.72,5575.4) ; C170.1@9478.64,5492.33 v4(9478.64,5575.4)
  Bottom Layer w23.62: C193.1@4181.1,5421.26 4179.13,5423.23 4179.13,5431.1 4190.95,5442.91 v4(4251.97,5442.91) ; C193.1@4188.98,5399.61 v4(4251.97,5399.61)
  Bottom Layer w30: C2.1@507.93,1261.74 507.93,1262.81 v2(507.93,1346.74) ; C2.1@567.93,1261.74 567.93,1262.81 v2(567.93,1346.74) ; v4(4373.68,1163.45) C147.2@4433.68,1163.45 ; v4(4373.68,1203.45) C147.2@4433.68,1203.45 ; v4(4373.68,1243.45) C147.2@4433.68,1243.45
  Bottom Layer w39.37: F5.2@1060.28,3696.47 v1(1107.52,3696.47) v1(1131.14,3696.47) v1(1154.76,3696.47) v1@1158.7,3696.47 ; R174.1@2135.83,3716.54 v1(2135.83,3771.65) v1(2135.83,3799.21) v1(2135.83,3824.8) ; R175.1@2549.21,3923.23 v1(2549.21,3978.35) v1(2549.21,4005.91) v1(2549.21,4031.5) ; C142.2@8106.75,4086.61 C140.1@8236.22,4086.61 ; F4.2@11160.25,2921.25 11207.5,2968.5 v1(11248.03,2968.5) v1(11279.53,2968.5) ; F3.2@11279.53,3208.66 v1(11279.53,2968.5) ; v1(11307.09,2968.5) v1(11279.53,2968.5)
  Bottom Layer w49.21: v2@429.13,3204.72 v2(448.82,3204.72) v2(476.38,3204.72) 527.56,3204.72 R176.1@531.5,3204.72
  Bottom Layer w50: U16.2@1690.61,4423.45 1690.61,4326.52 1733.68,4283.45 ; D8.2@1740.37,3768.45 1818.68,3846.76 1818.68,3933.45 v2(1818.68,4013.45) ; v4(4373.68,1123.45) 4422.68,1074.45 C146.2@4443.31,1074.45 C146.2@4445.28,1074.45 ; J15.6@5905.51,4838.98 v4@5905.51,5049.69
  Bottom Layer w59.06: R179.1@8011.81,3765.75 8011.81,3822.83 8011.81,3858.27 8027.76,3874.21 8027.84,3874.3 C140.1@8240.16,4086.61
  Bottom Layer w70: C135.1@2960.63,1582.68 2960.63,1696.5 ; U10.3@2996.06,1709.45 3118.68,1709.45 3153.68,1709.45 3193.68,1709.45 3207.68,1709.45 ; D4.2@3213.72,1590.55 3213.72,1688.45 v4@3213.72,1708.41
  Bottom Layer w78.74: C3.1@1842.44,4212.52 1974.41,4344.49 C166.1@1974.41,4409.45
  Bottom Layer w100: 1733.68,4283.45 1818.68,4198.45 1818.68,4176.89 v2(1818.68,4103.45) 1818.68,4088.45 v2(1818.68,4073.45) 1818.68,4058.45 v2@1818.68,4048.45 ; C3.1@1842.44,4176.89 C3.1@1842.44,4212.52
  Bottom Layer w118.11: C140.1@8240.16,4086.61 8421.26,4086.61 8909.45,4574.8 9566.93,4574.8 10035.43,5043.31 v2(10035.43,5594.49) v2(10035.43,5622.05) v2(10035.43,5649.61) v2(10035.43,5677.17) v2(10035.43,5704.72) v2@10035.43,5716.54
  Bottom Layer w120: v7(10998.68,5908.45) 11018.68,5888.45 v7(11038.68,5868.45) 11058.68,5848.45 v2(11078.68,5828.45) 11098.68,5808.45 11118.68,5788.45 11138.68,5768.45 11160.24,5746.9 SW6.1@11160.24,5699.13 SW6.2@11160.24,5549.13
  other v2: 421.26,3204.72 1793.68,4028.45 1843.68,4028.45 1818.68,4043.45 1793.68,4058.45 1843.68,4058.45 1793.68,4088.45 1843.68,4088.45 10007.87,5649.61 10062.99,5649.61 10007.87,5677.17 10062.99,5677.17 10007.87,5704.72 10062.99,5704.72 10035.43,5732.28 10035.43,5759.84 11038.68,5828.45 11118.68,5828.45
  other v3: 11160.24,5504.89 11121.92,5527.01 11198.55,5527.01 11121.92,5571.26 11198.55,5571.26 11160.24,5593.38 11160.24,5654.89 11121.92,5677.01 11198.55,5677.01 11121.92,5721.26 11198.55,5721.26 11160.24,5743.38
  other v4: 4323.68,1123.45 4323.68,1163.45 4323.68,1203.45 4323.68,1243.45 3118.68,1688.45 3153.68,1688.45 3193.68,1688.45 3223.68,1708.45 3118.68,1728.45 3153.68,1728.45 3193.68,1728.45
  other v7: 10998.68,5868.45 11078.68,5868.45 11038.68,5908.45
5V0D: C259.2 R182.1 R187.2 U49.12 | length 728.4
  Bottom Layer w7.87: U49.12@4244.37,4483.46 4294.49,4483.46 4304.52,4493.5 4526.19,4493.5 4716.54,4303.15 C259.2@4747.05,4303.15 4747.05,4346.54 R182.1@4748.03,4347.52 ; C259.2@4748.03,4311.02 4748.03,4346.93 R182.1@4748.03,4347.52 ; R182.1@4748.03,4349.92 R182.1@4748.03,4347.52 ; R187.2@4789.8,4389.29 R182.1@4748.03,4347.52
5VUSW: D1.2 F1.2 SW6.3
  other v2: 9658,5354 9693,5354 9728,5354 10264,5387 10299,5387 10334,5387 9658,5389 9693,5389 9728,5389 10264,5422 10299,5422 10334,5422 9658,5424 9693,5424 9728,5424 10264,5457 10299,5457 10334,5457 10264,5492 10299,5492 10334,5492
  other v3: 11160.24,5354.89 11121.92,5377.01 11198.55,5377.01 11121.92,5421.26 11198.55,5421.26 11160.24,5443.38
9V0: C133.1 C134.1 C235.1 C236.1 C237.1 C238.1 C239.1 C240.1 C241.1 C242.1 C243.1 C244.1 C245.1 C246.1 C247.1 C248.1 C249.1 C250.1 C251.1 C252.1 C253.1 LCD1.33 LCD1.34 R41.2 R43.2 R57.2 TP6.1 U9.2 U9.3 U9.6 U9.7 U29.3 U30.3 U31.3 U32.3 U33.3 U34.3 U35.3 U36.3 U37.3 U38.3 U39.3 U40.3 U41.3 U42.3 U43.3 U44.3 U45.3 U46.3 U47.3 | length 25673
  Top Layer w10: LCD1.33@8448.82,2582.68 8358.27,2582.68 v1(8350.39,2590.55) 8362.21,2602.36 LCD1.34@8448.82,2602.36
  Top Layer w25: v1(7929.13,2633.86) 8003.27,2633.86 8023.68,2613.45 8183.68,2613.45 8206.58,2590.55 v1(8350.39,2590.55)
  MidLayer1 w11.81: v2(8149.61,3397.64) 8196.85,3397.64 8334.65,3259.84 8334.65,2704.73 8350.39,2688.98 8350.39,2370.26 8226.72,2246.59 8226.72,1965.28 8681.8,1510.2 8762.17,1510.2 8902,1650.04 v1@8902,1734
  MidLayer2 w11.81: v2(8149.61,3397.64) 8406.95,3397.64 8976.38,3967.06 v2(8976.38,4216.54)
  MidLayer4 w11.81: v2(8976.38,4216.54) 8976.38,4260.63 9108.19,4392.45 9256.12,4540.38 9728.93,4540.38 10005.32,4816.78 10127.4,4816.78 10467,5156.37 10467,5334.02 TP6.1@10514.94,5381.97
  MidLayer3 w19.68: v1(665.55,3456.69) 665.55,3555.32 ; v1(813.19,3456.69) 813.19,3556.89 ; v1(960.83,3456.69) 960.83,3551.38 ; v1@1110.24,3456.69 1110.24,3555.12 ; v1(2417.52,4362.2) 2417.52,4436.81 ; v1(2565.16,4362.2) 2565.16,4435.24 ; v1(2712.8,4362.2) 2712.8,4432.87 ; v1(2860.43,4362.2) 2860.43,4435.24 ; v1(3008.07,4362.2) 3008.07,4436.81 ; v1(3155.71,4362.2) 3155.71,4435.24 ; v1(3303.35,4362.2) 3303.35,4437.01 ; v1(3421.26,4362.2) 3421.26,4437.01 ; v1(3598.62,4362.2) 3598.62,4437.01 ; v1(3746.26,4362.2) 3746.26,4437.01 ; v2(7806.1,4247.05) 7806.1,4298.23 ; v2(7885.83,4248.03) 7885.83,4303.15 ; 7885.83,4311.02 8921.26,4311.02 8976.38,4255.91 v2(8976.38,4216.54)
  MidLayer3 w59.06: 7000,4311.02 7889.76,4311.02
  MidLayer3 w78.74: v1(223.61,3455.59) 223.61,3539.61 243.06,3559.06 1134.94,3559.06 ; 980.32,3559.06 980.32,4220.47 1196.85,4437.01 3842.01,4437.01 4012.76,4607.76 4899.24,4607.76 5100.43,4406.57 6904.45,4406.57 7000,4311.02
  Bottom Layer w10: C245.1@648.72,3553.15 665.35,3536.52 U40.3@665.35,3503.94 ; v1(665.55,3456.69) U40.3@665.55,3503.94 ; C242.1@796.36,3553.15 813.19,3536.32 U37.3@813.19,3503.94 v1(813.19,3456.69) ; C244.1@944,3553.15 960.83,3536.32 U34.3@960.83,3503.94 v1(960.83,3456.69) ; C236.1@1091.63,3553.15 1108.46,3536.32 U31.3@1108.46,3503.94 v1(1108.46,3456.69) ; C252.1@2400.69,4458.66 2417.52,4441.83 U38.3@2417.52,4409.45 v1(2417.52,4362.2) ; C250.1@2548.33,4458.66 2565.16,4441.83 U41.3@2565.16,4409.45 v1(2565.16,4362.2) ; C248.1@2695.96,4458.66 2712.8,4441.83 U35.3@2712.8,4409.45 v1(2712.8,4362.2) ; C243.1@2843.6,4458.66 2860.43,4441.83 U32.3@2860.43,4409.45 v1(2860.43,4362.2) ; C241.1@2993.11,4458.66 3008.07,4443.7 U29.3@3008.07,4409.45 v1(3008.07,4362.2) ; C249.1@3138.88,4458.66 3155.71,4441.83 U42.3@3155.71,4409.45 v1(3155.71,4362.2) ; C238.1@3286.52,4458.66 3303.35,4441.83 U30.3@3303.35,4409.45 v1(3303.35,4362.2) ; v1(3421.26,4362.2) 3437.01,4362.2 3450.98,4376.18 U36.3@3450.98,4409.45 3450.98,4441.83 C247.1@3434.15,4458.66 ; C239.1@3581.79,4458.66 3598.62,4441.83 U33.3@3598.62,4409.45 v1(3598.62,4362.2) ; C237.1@3729.43,4458.66 3746.26,4441.83 U39.3@3746.26,4409.45 v1(3746.26,4362.2) ; v2(7806.1,4247.05) C235.1@7806.1,4045.28 7806.1,4024.61 7821.06,4009.65 U44.3@7821.06,3976.38 ; v2(7885.83,4248.03) 7885.83,4208.66 8012.8,4081.69 C240.1@8012.8,4045.28 8012.8,4022.64 8027.76,4007.68 U46.3@8027.76,3976.38
  Bottom Layer w11.81: C134.1@7471.46,2543.31 7471.46,2692.05 C133.1@7488.07,2708.66 C133.1@7488.07,2712.6 ; R43.2@7889.76,2627.48 7922.76,2627.48 v1(7929.13,2633.86)
  Bottom Layer w12: C246.1@206.89,3556.84 223.61,3540.13 U43.3@223.61,3502.9 v1(223.61,3455.59)
  Bottom Layer w15.75: C251.1@5334.73,1142.12 5349.69,1157.08 U45.3@5417.41,1157.08 5417.41,1168.41 5519,1270 5856,1270 5890,1304 6097,1304 6123,1278 6170,1278 ; 6163,1278 6170,1285 ; U47.3@6473,1160.1 6413.16,1160.1 C253.1@6398.2,1145.14 6256.86,1145.14 6170,1232 6170,1366 6301,1497 6532,1497 6661.63,1626.63 7051.71,1626.63 7170.71,1745.62 8888.53,1745.62 v1(8901,1733.15) ; U9.6@7448.82,2876.77 7375.2,2876.77 7375.2,2713.78 7376.38,2712.6 7484.13,2712.6 C133.1@7488.07,2708.66 ; 8821,1745.62 8841.01,1765.63 R41.2@8841.01,1799.21
  Bottom Layer w19.68: C133.1@7470.37,2735.87 v2(7470.37,2771.3) ; C133.1@7509.74,2735.87 v2(7509.74,2771.3)
  Bottom Layer w25: U9.2@7653.54,2926.77 7710.44,2926.77 7728.24,2908.98 R57.2@7771.65,2908.98 7880.71,2908.98 7929.13,2860.56 v1(7929.13,2633.86)
  other v2: 7518.49,2867.5 7549.98,2867.5 7581.48,2867.5 7517.5,2899 7580.5,2899 7518.49,2930.5 7549.98,2930.5 7581.48,2930.5
16V5: C116.1 C132.1 C139.2 C143.1 C144.2 D5.2 LCD1.1 LCD1.42 LCD1.44 R63.2 TP8.1 U9.1 | length 8510.8
  Top Layer w7.87: LCD1.1@8448.82,1952.76 8496.06,1952.76 8503.94,1944.88 8539.37,1944.88 8570.87,1976.38 8570.87,2531.5 8543.31,2559.06 8543.31,2759.84 8519.69,2783.47 8500,2783.47 ; LCD1.42@8448.82,2759.84 8500,2759.84 8500,2783.47 ; LCD1.44@8448.82,2799.21 8500,2799.21 8500,2783.47
  Top Layer w11.81: v2(8248.03,2893.7) 8267.72,2874.02 8267.72,2822.84 8291.34,2799.21 LCD1.44@8448.82,2799.21 LCD1.44@8460.63,2799.21
  MidLayer1 w11.81: v2(8110.24,3397.64) 8145.67,3362.21 8161.42,3362.21 8248.03,3275.59 v2(8248.03,2893.7)
  MidLayer2 w11.81: v2(8110.24,3397.64) 8137.64,3425.04 8399.69,3425.04 8933.07,3958.43 v2(8933.07,4216.54)
  MidLayer4 w11.81: v2(8933.07,4216.54) 8933.07,4256.3 9233.96,4557.19 9721.96,4557.19 9998.36,4833.59 10120.44,4833.59 10450.19,5163.34 10450.19,5417.21 TP8.1@10514.94,5481.97
  Bottom Layer w12: R63.2@6546.77,2744.1 6641.62,2744.1 6694.6,2797.08 6694.6,2820.87 ; 6641.72,2873.75 6641.73,2889.76
  Bottom Layer w23.62: C144.2@6385.83,2744.1 6385.83,2804.76 6425.35,2844.29 6425.35,2885.83 ; 6641.73,2889.76 6783.46,3031.5 7524.41,3031.5 7579.13,2976.77 U9.1@7653.54,2976.77 7912.99,2976.77 7996.06,2893.7 v2(8248.03,2893.7)
  Bottom Layer w40: C116.1@5952.76,2885.83 6629.64,2885.83 6694.6,2820.87 D5.2@6775.59,2820.87
-7V5: C128.1 C129.2 D2.1 LCD1.6 R56.2 TP5.1 | length 7436.5
  Top Layer w15: v1(8389.76,2051.18) LCD1.6@8448.82,2051.18
  MidLayer1 w11.81: v2(8149.61,3452.76) 8216.54,3452.76 8417.32,3251.97 8417.32,2078.74 v1(8389.76,2051.18)
  MidLayer2 w11.81: v2(8149.61,3452.76) 8388.39,3452.76 8889.76,3954.13 v2(8889.76,4216.54)
  MidLayer2 w15: v2(7338.58,2897.64) 7338.58,2458.55 7745.95,2051.18 v1(8389.76,2051.18)
  MidLayer4 w11.81: v2(8889.76,4216.54) 8889.76,4251.97 9211.79,4574 9715,4574 9991.4,4850.4 10113.48,4850.4 10433.38,5170.3 10433.38,5500.4 TP5.1@10514.94,5581.97
  Bottom Layer w11.81: R56.2@6929.13,2924.73 6929.13,2954.07 6939.52,2964.46 C128.1@7019.8,2964.46 ; C128.1@7027.56,2952.76 C128.1@7031.5,2952.76 ; v1(8389.76,2051.18) C129.2@8389.76,2081.69
  Bottom Layer w15: C128.1@7029.53,2954.73 7078.74,2905.51 7330.71,2905.51 v2(7338.58,2897.64) ; D2.1@7183.07,2856.3 7183.07,2905.06
A3V3_USB: C272.2 C273.1 NT5.2 U52.3 | length 620.3
  Top Layer w10: U52.3@8108.27,5201.38 v1(8108.27,5234.25)
  Bottom Layer w19.68: C272.2@8110.68,5193.1 8108.27,5195.51 v1(8108.27,5234.25) 8190.75,5234.25 8370.93,5054.07 C273.1@8470.68,5054.07 NT5.2@8578.93,5054.07
AC16V: C131.1 D5.1 L1.2 U11.1 | length 1561.4
  Bottom Layer w15.75: L1.2@6177.17,2681.1 L1.2@6181.1,2677.17
  Bottom Layer w19.68: D5.1@6775.59,2657.48 6858.27,2657.48 6889.76,2625.99 7236.22,2625.99 7283.46,2673.23 C131.1@7283.46,2722.44 C131.1@7283.46,2724.41
  Bottom Layer w30: L1.2@6181.1,2677.17 6377.95,2677.17 6385.83,2669.29 U11.1@6385.9,2647
  Bottom Layer w40: L1.2@6182.3,2481.2 6183.18,2480.32 6712.6,2480.32 6775.59,2543.31 D5.1@6775.59,2657.48
AD.AIN0: C5.1 HDR7.9 TS1.6 U1.1 | length 3067.2
  MidLayer2 w7.87: HDR7.9@8868.5,616.54 8868.5,548.82 8964.57,452.76 9037.91,452.76 TS1.6@9190.67,300
  MidLayer4 w7.87: v1(8270.97,1228.01) 8300.13,1198.85 8300.13,981.87 8483.87,798.13 8768.71,798.13 8826,740.83 8826,659.04 HDR7.9@8868.5,616.54
  Bottom Layer w7.87: U1.1@7695.65,1530.45 U1.1@7704.65,1530.45 7890.85,1530.45 7999.67,1421.62 8559.58,1421.62 8624.87,1356.33 8624.87,1229.96 8597.17,1202.26 8517.99,1202.26 8497.02,1223.23 8413.23,1223.23 8395,1205 8293.98,1205 v1(8270.97,1228.01) v1@8270.97,1229 ; C5.1@8270.97,1256.86 v1@8270.97,1229 ; v1@8271.46,1228.51 v1@8270.97,1229
AD.AIN1: C6.1 HDR7.10 TS1.7 U1.2 | length 2976.3
  MidLayer2 w7.87: HDR7.10@8868.5,716.54 8918.5,666.54 8918.5,553.94 8996.06,476.38 9114.29,476.38 TS1.7@9290.67,300
  MidLayer4 w7.87: v1(8370.97,1228.01) 8313,1170.04 8313,992 8494,811 8774.04,811 HDR7.10@8868.5,716.54
  Bottom Layer w7.87: U1.2@7695.65,1504.86 U1.2@7704.65,1504.86 7898.23,1504.86 7994.34,1408.75 8554.25,1408.75 8612,1351 8612,1235.29 8591.84,1215.14 8523.33,1215.14 8502.36,1236.11 8407.9,1236.11 8399.8,1228.01 v1(8370.97,1228.01) C6.1@8370.97,1256.86
AD.AIN2: C7.1 HDR7.11 TS1.8 U1.3 | length 2702.5
  MidLayer2 w7.87: HDR7.11@8968.5,616.54 8968.5,559.06 9027.56,500 9190.67,500 TS1.8@9390.67,300
  MidLayer4 w7.87: v1(8499.81,1256.86) 8715.5,1041.17 8715.5,951.33 8919,747.83 8919,666.04 HDR7.11@8968.5,616.54
  Bottom Layer w7.87: U1.3@7695.65,1479.27 U1.3@7704.65,1479.27 7905.62,1479.27 7989.01,1395.87 8546.13,1395.87 8599,1343 ; C7.1@8470.97,1256.86 v1(8499.81,1256.86) 8528.66,1228.01 8586.51,1228.01 8599.13,1240.63 8599.13,1266.25 ; 8548.92,1395.87 8599,1345.79 8599,1343 ; 8599,1266.25 8599,1343
AD.AIN3: C8.1 HDR7.12 JP1.1 TS1.9 U1.4 | length 3673.9
  MidLayer2 w7.87: JP1.1@8385.83,251.97 8452.76,185.04 9375.71,185.04 TS1.9@9490.67,300 9310.69,479.98 ; HDR7.12@8968.5,716.54 9019.69,665.36 9019.69,562.99 9059.06,523.62 9267.72,523.62 9311.02,480.32
  MidLayer4 w7.87: v1(8542.12,1256.86) 8735,1063.98 8735,950.04 HDR7.12@8968.5,716.54
  Bottom Layer w7.87: U1.4@7695.65,1453.68 U1.4@7704.65,1453.68 7913,1453.68 7983.68,1383 8527,1383 8542.12,1367.88 v1(8542.12,1256.86) C8.1@8570.97,1256.86
AD.AOUT0: HDR7.5 TS1.2 U4.7 | length 2024.8
  MidLayer1 w7.87: HDR7.5@8668.5,616.54 8668.5,496.85 8715.95,449.4 8766.35,449.4 8790.67,425.08 TS1.2@8790.67,300
  Bottom Layer w7.87: U4.7@7736.23,1359.06 7694.48,1359.06 7665.94,1330.53 7665.94,1052.93 7890.89,827.98 8602.44,827.98 8621.04,809.38 8621.04,664 HDR7.5@8668.5,616.54
AD.AOUT1: HDR7.6 TS1.3 U4.8 | length 2052.1
  MidLayer1 w7.87: HDR7.6@8668.5,716.54 8719.57,665.47 8719.57,519.69 8762.87,476.38 8839.37,476.38 8890.67,425.08 TS1.3@8890.67,300
  Bottom Layer w7.87: U4.8@7736.23,1339.38 7693,1339.38 7678.82,1325.2 7678.82,1058.26 7896.22,840.86 8607.77,840.86 8633.91,814.71 8633.91,751.13 HDR7.6@8668.5,716.54
AD.AOUT2: HDR7.7 TS1.4 U4.9 | length 2078.9
  MidLayer1 w7.87: HDR7.7@8768.5,616.54 8768.5,551.18 8803.94,515.75 8900,515.75 8990.67,425.08 TS1.4@8990.67,300
  Bottom Layer w7.87: U4.9@7736.23,1319.69 7691.69,1319.69 7691.69,1063.6 7901.56,853.73 8613.1,853.73 8722,744.83 8722,657 8762.46,616.54 HDR7.7@8768.5,616.54
AD.AOUT3: HDR7.8 TS1.5 U4.10 | length 2089.8
  MidLayer1 w7.87: HDR7.8@8768.5,716.54 8817.99,667.05 8817.99,572.68 8843.43,547.24 8968.5,547.24 9090.67,425.08 TS1.5@9090.67,300
  Bottom Layer w7.87: U4.10@7736.23,1300.01 7715.01,1300.01 7704.57,1289.57 7704.57,1068.93 7906.89,866.61 8618.43,866.61 HDR7.8@8768.5,716.54
AD.I2C.SCL: EXTHDR1.25 EXTHDR2.25 EXTHDR3.25 HDR7.3 HDR_B1.5 R6.2 R8.1 | length 15408.7
  Top Layer w5: v1(6551.18,1244.1) HDR_B1.5@6551.18,1318.9
  Top Layer w7.87: v1(1614.17,3007.87) EXTHDR1.25@1614.17,3086.61 ; v1(3307.09,3271.65) EXTHDR3.25@3307.09,3409.45 ; v1(4094.49,3007.87) EXTHDR2.25@4094.49,3086.61
  MidLayer2 w5: v1(4094.49,3007.87) 4094.49,3027.56 4086.61,3035.43 4051.18,3035.43 4043.31,3027.56 4043.31,3003.94 3980.32,2940.95 3456.69,2940.95 3401.57,2996.06 3401.57,3244.1 3350.39,3295.28 3330.71,3295.28 v1(3307.09,3271.65) 2846.46,3271.65 2724.41,3149.61 2232.28,3149.61 2106.3,3023.62 1629.92,3023.62 v1(1614.17,3007.87) 1578.74,3043.31 1220.47,3043.31 1204.72,3027.56 1204.72,2948.82 1250.09,2903.45 2202.93,2903.45 2295.36,2811.02 2870.08,2811.02 2897.64,2838.58 4507.87,2838.58 4523.62,2822.84 4673.23,2822.84 4775.59,2925.2 5196.85,2925.2 5397.64,3125.98 5397.64,3188.98 5429.13,3220.47 5744.09,3220.47 5846.46,3118.11 5846.46,1610.24 5893.7,1562.99 6181.1,1562.99 6314.96,1429.13 6452.76,1429.13 6466.68,1415.21 6466.68,1226.23 6476.38,1216.54 6543.31,1216.54 6551.18,1224.41 v1(6551.18,1244.1) 7736.47,1244.1 7777,1203.57 7777,909 7815.92,870.08 8519.69,870.08 8627,977.39 8627,1319.86 8635.21,1328.06 8719,1328.06 8726,1321.06 8726,1167 8816,1077 8816,809.14 8779.86,773 8568.4,773 8531.2,735.8 8531.2,653.84 HDR7.3@8568.5,616.54
  Bottom Layer w5: v4(7777,1131) 7777,1221 7807.8,1251.8 R8.1@7842.6,1251.8
  Bottom Layer w7.87: R6.2@8670.97,1299.22 v1(8670.97,1328.06)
